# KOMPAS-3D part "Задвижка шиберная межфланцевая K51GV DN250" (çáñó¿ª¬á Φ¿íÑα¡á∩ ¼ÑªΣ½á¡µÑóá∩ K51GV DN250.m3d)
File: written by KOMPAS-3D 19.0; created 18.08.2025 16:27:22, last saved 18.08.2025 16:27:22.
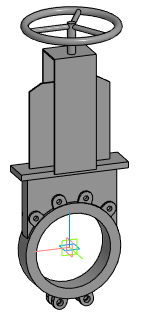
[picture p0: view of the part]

Document properties: Автор: Евгений; Полное имя файла: E:\Dendor Работа Сачек\3D для проектировщиков\2.4 Тип K51GV. Задвижка шиберная межфланцевая\stp_Задвижка шиберная K51GV DN50-400 с маховиком\Задвижка шиберная межфланцевая K51GV DN250.m3d

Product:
- Part/product: Задвижка шиберная межфланцевая K51GV DN250

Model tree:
1. Операция без истории:1  (labels: Задвижка шиберная межфланцевая K51GV DN250)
